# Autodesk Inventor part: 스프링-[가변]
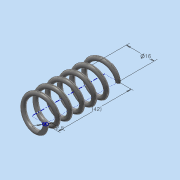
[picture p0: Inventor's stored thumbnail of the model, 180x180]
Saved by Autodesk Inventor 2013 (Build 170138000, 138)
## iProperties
Created: 2015-05
Part Number: 스프링-[가변]
Material: 강철, 탄소
Document SubType Name: Modeling
Designer: Administrator
Density: 7.87 g/cm^3
Mass: 11.4975 g
Surface Area: 23.7332 cm^2
Volume: 1.46093 cm^3
Author: Administrator
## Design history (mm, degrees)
sketch "스케치1"
  geometry: L1 (0, 0)-(8, 0); L2 (8, 0)-(8, 42); L3 (8, 42)-(0, 42); L4 (0, 42)-(0, 0); C1 r 1.25 at (8, 0)
  constraints: 8 end point, 2 parallel, 1 centre point, 1 coincident, 1 horizontal, 1 perpendicular
  dimensions: "d0" = 16 diameter of L2 L4; "d2" = 42 distance of L1.end L2.end (derived); "d3" = 2.5 diameter of C1
feature "코일1" sketch "스케치1" pitch "d4" = 10; turns "d6" = 6; dims "d5" = 42 (= d2), "d7" = 0, angle "d8" = 90 deg, angle "d9" = 90 deg, "d10" = 0, "d11" = 0
sketch "스케치2"
  geometry: L1 (-9.25, 0)-(-6.75, 0) reference; 1 further point
  constraints: 1 horizontal alignment
extrude "돌출1" cut sketch "스케치2" stored distance "d12" = 10; taper "d13" = 0 deg
node "작업 평면1"
sketch "스케치3"
  geometry: L1 (2.5, 0)-(0, 0) reference; 1 further point
  constraints: 1 horizontal alignment
extrude "돌출2" cut sketch "스케치3" stored distance "d14" = 10; taper "d15" = 0 deg
node "솔리드1"
node "절단 모서리 투영1"
node "절단 모서리 투영2"
